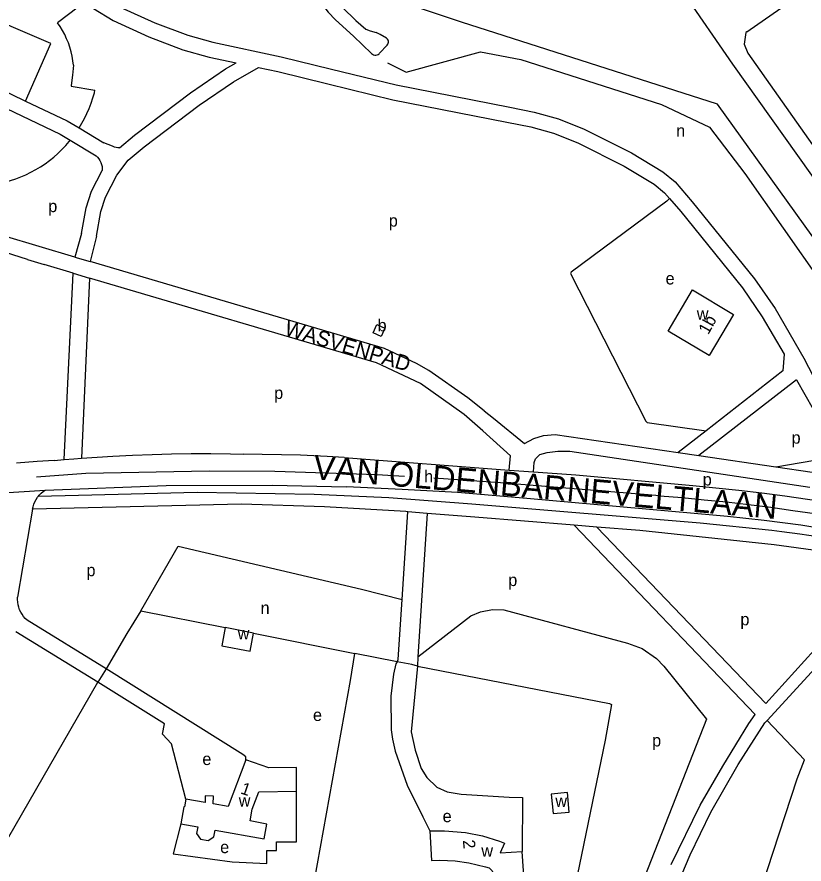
# Model space of a CAD drawing. Extents: x 162427 to 165104, y 384242 to 386287.
# Drawn here: x 162833.6 to 163093, y 385284.6 to 385563.5 of the extents above; entities that cross this region are included whole.
import ezdxf

# ---------------------------------------------------------------- set-up
doc = ezdxf.new("R2010")
doc.units = 0
for name, color, linetype in [('BLT_Basislijn', 7, 'Continuous'), ('BLT_Bebouwing', 7, 'Continuous'), ('BLT_Centroide', 7, 'Continuous'), ('BLT_Huisnummer', 7, 'Continuous'), ('BLT_Straatnaam', 7, 'Continuous'), ('BLT_Straatnaam_hoofdweg', 7, 'Continuous'), ('BLT_Vlakafsluiter', 7, 'Continuous')]:
    doc.layers.add(name, color=color, linetype=linetype)

msp = doc.modelspace()

# ---------------------------------------------------------------- linework, layer by layer
at = {"layer": 'BLT_Basislijn'}
for p, q in [((163074.07, 385558.59), (163110.58, 385584.14)), ((162853.74, 385566.74), (162846.99, 385561.61)), ((162953.08, 385551.58), (162955.6, 385554.29)), ((162824.38, 385541.58), (162836.46, 385535.85)), ((162851.46, 385540.73), (162859.33, 385539.43)), ((162854.09, 385526.99), (162862.24, 385522.09)), ((162851.16, 385522.92), (162859.67, 385517.81)), ((162865.15, 385520.94), (162862.24, 385522.09)), ((162837.14, 385483.62), (162842.56, 385481.97)), ((162852.73, 385484.48), (162857.74, 385483.02)), ((162852.12, 385479.12), (162842.56, 385481.97)), ((162849.18, 385417.79), (162852.12, 385479.12)), ((162852.12, 385479.12), (162857.5, 385477.49)), ((162857.5, 385477.49), (162854.91, 385418.26)), ((163090.51, 385444.08), (163058.29, 385419.08)), ((163060.7, 385427.28), (163051.43, 385420.09)), ((163010.97, 385426.02), (163051.43, 385420.09)), ((162941.38, 385418.48), (162935.87, 385418.75)), ((162941.38, 385418.48), (162995.84, 385414.29)), ((163051.43, 385420.09), (163058.29, 385419.08)), ((163058.29, 385419.08), (163083.72, 385415.35)), ((162840.26, 385417.1), (162833.42, 385416.61)), ((162845.92, 385417.51), (162840.26, 385417.1)), ((162845.92, 385417.51), (162849.18, 385417.79)), ((162995.84, 385414.29), (163003.86, 385413.73)), ((163083.72, 385415.35), (163095.61, 385413.61)), ((162838.73, 385401.42), (162833.82, 385372.49)), ((162960.57, 385371.71), (162962.45, 385400.6)), ((162968.83, 385400.07), (162965.69, 385352.84)), ((163017.2, 385396.15), (162984.46, 385398.77)), ((163017.2, 385396.15), (163076.9, 385333.85)), ((163024.7, 385395.55), (163017.2, 385396.15)), ((163024.7, 385395.55), (163080.36, 385337.47)), ((163080.36, 385337.47), (163121.81, 385383.22)), ((162874.46, 385367.97), (162902.26, 385362.46)), ((162863.02, 385348.85), (162836.97, 385364.91)), ((162860.27, 385344.53), (162833.28, 385361.09)), ((162911.61, 385360.62), (162944.93, 385353.93)), ((162958.89, 385351.17), (162944.93, 385353.93)), ((162965.69, 385352.84), (162965.6, 385349.76)), ((162863.02, 385348.85), (162860.27, 385344.53)), ((162963.73, 385350.33), (162958.89, 385351.17)), ((162965.6, 385349.76), (162963.73, 385350.33)), ((163080.8, 385331.81), (163093.14, 385318.96))]:
    msp.add_line(p, q, dxfattribs=at)
for points in [[(162761.2, 385522.51), (162766.48, 385530.94), (162788.41, 385566), (162791.77, 385571.66), (162794.41, 385575.12), (162797.5, 385577.98), (162799.64, 385579.2), (162802.6, 385580.51), (162808.08, 385582.95), (162814.65, 385584.84), (162822.48, 385586.18), (162824.7, 385586.14), (162827.51, 385585.55), (162831.36, 385584.11), (162837.28, 385580.8), (162858.83, 385566.3), (162865.3, 385562.36), (162877.09, 385557.03), (162888.31, 385552.73), (162896.96, 385550.32), (162905.89, 385548.44)], [(162922.1, 385587.98), (162922.54, 385586.04), (162923.76, 385585.16), (162926.09, 385582.79), (162927.4, 385581.27), (162929.16, 385579.75), (162932.92, 385576.17), (162934.92, 385574.11), (162938.91, 385568.91), (162940.88, 385566.6), (162945.28, 385562.36), (162948.62, 385559.54), (162949.98, 385558.93), (162952, 385558.44)], [(162916.4, 385584.93), (162917.45, 385584.86), (162918.26, 385584.17), (162922.97, 385580), (162926.8, 385576.15), (162931.92, 385570.8), (162936.11, 385565.09), (162938.57, 385562.64), (162944.56, 385557.26), (162950.46, 385551.47)], [(163053.01, 385571.86), (163069.39, 385548), (163103.5, 385500), (163138.29, 385450.78), (163142.13, 385444.88), (163144.53, 385439.97), (163145.57, 385436.28), (163145.97, 385432.21), (163145.34, 385429.37)], [(162867.64, 385566.79), (162879.02, 385561.65), (162889.87, 385557.49), (162898.15, 385555.18), (162920.71, 385550.41), (162937.22, 385546.38), (162958.59, 385541.16), (162996.04, 385533.78), (163004.04, 385532.2), (163012.04, 385530.03), (163020.48, 385526.63), (163036.1, 385518.74), (163046.44, 385512.58), (163050.5, 385509.22), (163056.14, 385502.71), (163076.67, 385477.33), (163083.41, 385467.5), (163092.94, 385451.2)], [(163116.12, 385462.98), (163064.49, 385534.84), (162980.05, 385561.82), (162964.58, 385567.01), (162964.39, 385567.3)], [(162836.46, 385535.85), (162844.79, 385554.75), (162818.33, 385566.15), (162812.27, 385551.72), (162801.8, 385556.33), (162796.54, 385544.37), (162805.66, 385540.36), (162811.36, 385541.63)], [(162852.25, 385547.65), (162852.07, 385549.14), (162851.81, 385550.63), (162851.47, 385552.1), (162851.06, 385553.54), (162850.56, 385554.97), (162849.99, 385556.36), (162849.35, 385557.73), (162848.64, 385559.06), (162847.86, 385560.35), (162846.99, 385561.61)], [(162955.41, 385556.57), (162953.31, 385557.79), (162952, 385558.44)], [(163074.07, 385558.59), (163073.78, 385558.45), (163073.18, 385554.63), (163074.49, 385551.59), (163145.21, 385451.38), (163149.2, 385444.54), (163150.89, 385439.83), (163151.59, 385436.07), (163151.22, 385429.35), (163150.93, 385427.49)], [(162955.6, 385554.29), (162955.81, 385554.56), (162955.95, 385554.88), (162956.02, 385555.22), (162956.01, 385555.57), (162955.92, 385555.9), (162955.76, 385556.21), (162955.53, 385556.47), (162955.41, 385556.57)], [(162950.46, 385551.47), (162950.77, 385551.24), (162951.12, 385551.08), (162951.49, 385551), (162951.88, 385550.99), (162952.26, 385551.06), (162952.61, 385551.21), (162952.93, 385551.43), (162953.08, 385551.58)], [(162955.7, 385548.45), (162961.84, 385545.4), (162986.37, 385552), (162999.63, 385549.49), (163045.96, 385534.68), (163061.82, 385527.19), (163073.48, 385511.96), (163123.98, 385439.93), (163131.85, 385428.71), (163141.25, 385424.64)], [(162852.25, 385547.65), (162851.92, 385544.32), (162851.5, 385541.01), (162851.46, 385540.73)], [(162859.77, 385491.36), (162861.22, 385499.46), (162862.81, 385504.19), (162866.55, 385511.46), (162870.27, 385516.35), (162875.49, 385520.72), (162893.66, 385534.49), (162904.99, 385542.15), (162913.21, 385546.89)], [(162867.37, 385520.44), (162872.37, 385524.63), (162890.75, 385538.56), (162902.34, 385546.4), (162905.89, 385548.44)], [(162913.21, 385546.89), (162919.6, 385545.54), (162936.03, 385541.53), (162957.52, 385536.28), (162995.08, 385528.87), (163002.9, 385527.33), (163010.44, 385525.28), (163018.41, 385522.07), (163033.69, 385514.36), (163043.55, 385508.48), (163046.99, 385505.63), (163048.59, 385503.79)], [(162854.09, 385526.99), (162855.03, 385528.54), (162855.89, 385530.14), (162856.69, 385531.77), (162857.41, 385533.44), (162858.05, 385535.13), (162858.62, 385536.86), (162859.12, 385538.6), (162859.33, 385539.43)], [(162822.45, 385536.96), (162847.84, 385524.91), (162851.16, 385522.92)], [(162836.46, 385535.85), (162850.21, 385529.32), (162854.09, 385526.99)], [(162852.73, 385484.48), (162829.23, 385491.51), (162815.77, 385495.86), (162796.25, 385503.93), (162783.67, 385510.02), (162761.2, 385522.51)], [(162822.62, 385507.91), (162824.42, 385508.1), (162826.22, 385508.37), (162828, 385508.71), (162829.76, 385509.14), (162831.51, 385509.64), (162833.23, 385510.22), (162834.92, 385510.87), (162836.59, 385511.6), (162838.21, 385512.4), (162839.81, 385513.27), (162841.36, 385514.21), (162842.87, 385515.21), (162844.33, 385516.29), (162845.75, 385517.42), (162847.11, 385518.62), (162848.42, 385519.88), (162849.68, 385521.19), (162850.87, 385522.56), (162851.16, 385522.92)], [(162867.37, 385520.44), (162866.8, 385520.44), (162866.25, 385520.52), (162865.71, 385520.68), (162865.15, 385520.94)], [(162837.14, 385483.62), (162807.68, 385493), (162793.85, 385498.57), (162759.31, 385518.12)], [(162859.67, 385517.81), (162860.16, 385517.34), (162860.6, 385516.81), (162860.97, 385516.24), (162861.27, 385515.63), (162861.49, 385514.98), (162861.64, 385514.32), (162861.71, 385513.64), (162861.71, 385512.96)], [(162854.85, 385492.24), (162856.37, 385500.7), (162858.19, 385506.14), (162861.71, 385512.96)], [(163048.59, 385503.79), (163047.8, 385502.89), (163016.21, 385479.55), (163015.99, 385479.01), (163040.81, 385430.41), (163041.32, 385430.02), (163060.7, 385427.28)], [(163048.59, 385503.79), (163052.31, 385499.5), (163072.66, 385474.34), (163079.19, 385464.82), (163086.37, 385452.53)], [(162854.85, 385492.24), (162852.73, 385484.48)], [(162859.77, 385491.36), (162857.74, 385483.02)], [(162987.6, 385433.84), (162982.19, 385438.08), (162969.31, 385447.1), (162965.27, 385449.46), (162954.72, 385454.34), (162857.74, 385483.02)], [(162995.84, 385414.29), (162996.24, 385418.97), (162987.15, 385427.3), (162980.93, 385432.66), (162966.54, 385442.85), (162952.07, 385449.62), (162857.5, 385477.49)], [(163086.37, 385452.53), (163085.95, 385446.99), (163060.7, 385427.28)], [(163092.94, 385451.2), (163100.4, 385436.75), (163108.94, 385419.04)], [(163090.51, 385444.08), (163095.96, 385434.43), (163102.8, 385420.27), (163102.7, 385419.23), (163102.04, 385418.37)], [(162987.6, 385433.84), (162990.63, 385431.42), (163000.82, 385423.08), (163003.92, 385424.75), (163007.1, 385425.75), (163010.97, 385426.02)], [(162854.91, 385418.26), (162865.23, 385418.94), (162871.68, 385419.26), (162878.14, 385419.5), (162884.59, 385419.66), (162891.05, 385419.74), (162897.51, 385419.73), (162903.96, 385419.65), (162908.15, 385419.56)], [(162935.87, 385418.75), (162927.03, 385419.18), (162908.15, 385419.56)], [(163003.86, 385413.73), (163004.08, 385416.82), (163004.53, 385418.02), (163005.92, 385419.41), (163008.29, 385420.11), (163011.86, 385420.54), (163015.8, 385420.54), (163094.87, 385408.66)], [(163083.72, 385415.35), (163100.41, 385418.22), (163102.04, 385418.37)], [(162849.18, 385417.79), (162852.35, 385418.07), (162854.91, 385418.26)], [(162840.06, 385412.11), (162856.33, 385413.29), (162896.97, 385414.1), (162918.55, 385413.98), (162952.2, 385412.92), (162961.33, 385412.37)], [(163003.86, 385413.73), (163017.77, 385412.76), (163056.37, 385409.27)], [(163045.45, 385405.86), (162992.99, 385410.16), (162970.95, 385411.68)], [(162840.56, 385405.58), (162840.98, 385406.1), (162841.59, 385406.73), (162842.25, 385407.3), (162842.86, 385407.73)], [(162842.86, 385407.73), (162882.79, 385409.24), (162917.68, 385409.39), (162942.18, 385408.77)], [(162978.79, 385406.89), (162960.53, 385407.96), (162942.18, 385408.77)], [(163056.37, 385409.27), (163063.93, 385408.53), (163071.49, 385407.71), (163079.04, 385406.81), (163086.58, 385405.83), (163094.1, 385404.77), (163101.62, 385403.64), (163109.12, 385402.42), (163116.61, 385401.12), (163121.43, 385400.25)], [(162838.73, 385401.42), (162838.92, 385402.27), (162839.19, 385403.1), (162839.53, 385403.91), (162839.95, 385404.68), (162840.43, 385405.41), (162840.56, 385405.58)], [(162983.51, 385403.11), (162956.12, 385405.19), (162931.57, 385406.33), (162893.03, 385406.89), (162853.93, 385405.95), (162840.56, 385405.58)], [(163064.08, 385399.33), (163001.65, 385405), (162978.79, 385406.89)], [(163045.45, 385405.86), (163052.78, 385405.26), (163060.1, 385404.58), (163067.41, 385403.82), (163074.71, 385402.98), (163082.01, 385402.06), (163089.29, 385401.06), (163096.57, 385399.98), (163103.83, 385398.82), (163111.08, 385397.58), (163115.29, 385396.83)], [(162962.45, 385400.6), (162961.79, 385400.66), (162934.97, 385402.17), (162907.58, 385403.11), (162838.73, 385401.42)], [(163082.4, 385394.42), (163058.69, 385396.88), (162983.51, 385403.11)], [(162968.83, 385400.07), (162962.45, 385400.6)], [(162984.46, 385398.77), (162968.83, 385400.07)], [(163157.11, 385381.75), (163151.27, 385383.45), (163145.4, 385385.07), (163139.52, 385386.61), (163133.62, 385388.08), (163127.7, 385389.46), (163121.76, 385390.77), (163115.81, 385392), (163109.84, 385393.16), (163103.86, 385394.23), (163097.86, 385395.23), (163091.85, 385396.14), (163085.82, 385396.98), (163079.79, 385397.74), (163073.75, 385398.41), (163067.7, 385399.01), (163064.08, 385399.33)], [(163083.15, 385389.69), (163038.86, 385394.42), (163024.7, 385395.55)], [(163161.53, 385377.68), (163155.81, 385379.41), (163150.06, 385381.05), (163144.29, 385382.62), (163138.5, 385384.11), (163132.69, 385385.53), (163126.87, 385386.86), (163121.02, 385388.12), (163115.16, 385389.3), (163109.29, 385390.4), (163103.4, 385391.43), (163097.49, 385392.37), (163091.58, 385393.23), (163085.65, 385394.02), (163082.4, 385394.42)], [(162874.46, 385367.97), (162886.68, 385389.28), (162947.16, 385375.1), (162960.57, 385371.71)], [(163121.81, 385383.22), (163121.48, 385383.3), (163115.93, 385384.46), (163110.35, 385385.55), (163104.76, 385386.55), (163099.16, 385387.48), (163093.54, 385388.33), (163087.92, 385389.1), (163083.15, 385389.69)], [(163129.12, 385354.39), (163124.66, 385363.72), (163121.61, 385375.54), (163121.26, 385375.58), (163118.48, 385372.93), (163080.8, 385331.81)], [(162836.97, 385364.91), (162836.35, 385365.49), (162835.78, 385366.14), (162835.28, 385366.83), (162834.85, 385367.57), (162834.49, 385368.34), (162834.2, 385369.15), (162833.98, 385369.98), (162833.85, 385370.82), (162833.79, 385371.68), (162833.82, 385372.49)], [(162958.89, 385351.17), (162959.24, 385351.94), (162960.57, 385371.71)], [(162965.69, 385352.84), (162983.21, 385366.35), (162986.39, 385367.67), (162990.33, 385368.38), (162994.07, 385368.33), (163034.75, 385357.35), (163039.59, 385355.6), (163044.36, 385352.23), (163046.8, 385349.75), (163060.77, 385332.28), (163028.94, 385251.16), (163027.67, 385248.94), (163019.63, 385237.96), (163009.41, 385217.72), (162996.31, 385190.48), (162992.28, 385189.49)], [(162874.46, 385367.97), (162869.78, 385360.52), (162863.02, 385348.85)], [(162926.02, 385245.83), (162927.74, 385257.26), (162943.57, 385345.06), (162944.93, 385353.93)], [(162909.06, 385318.93), (162909.04, 385319.93), (162908.03, 385320.69), (162863.02, 385348.85)], [(162958.89, 385351.17), (162958.43, 385350.47), (162957.68, 385347.08), (162956.76, 385339.89), (162956.88, 385328.83), (162957.32, 385325.72), (162958.28, 385321.8), (162962.24, 385310.61), (162967.38, 385300.17), (162969.63, 385295.5)], [(162965.6, 385349.76), (162963.55, 385328.15), (162964.82, 385322.04), (162966.83, 385316), (162968.7, 385313.06), (162972.01, 385309.91), (162975.36, 385308.36), (162980.02, 385307.56), (162995.85, 385306.61)], [(162965.6, 385349.76), (163028.81, 385337.47), (163029.51, 385337.1), (163027.38, 385325.35), (163011.22, 385246.68), (163005.62, 385234.36), (162999.14, 385223.47), (162982.5, 385215.51)], [(162834.05, 385253.2), (162827.34, 385264.48), (162824.86, 385269.68), (162823.82, 385274.93), (162824.44, 385281.17), (162826.19, 385285.52), (162860.27, 385344.53)], [(162889.31, 385305.99), (162884.53, 385324.17), (162881.62, 385327.4), (162882.18, 385330.71), (162860.27, 385344.53)], [(163049.23, 385284.4), (163058.77, 385304.03), (163066.15, 385316.81), (163074.73, 385330.89), (163076.9, 385333.85)], [(163050.17, 385099.92), (163043.85, 385110.36), (163040, 385117.94), (163035.74, 385127.32), (163031.74, 385137.7), (163028.59, 385148.33), (163025.01, 385164.11), (163024.68, 385166.51), (163024.35, 385174.43), (163024.41, 385185.63), (163024.9, 385191.54), (163028.4, 385210.46), (163031.8, 385223.24), (163039.95, 385248.68), (163044.77, 385262.46), (163055.44, 385287.67), (163062.28, 385301.64), (163071.2, 385317.38), (163080.08, 385331.06), (163080.8, 385331.81)], [(163050.17, 385099.92), (163057.2, 385114.94), (163058.93, 385119.41), (163060.54, 385129.27), (163060.68, 385134.28), (163056.7, 385183.49), (163052.96, 385210.26), (163053.62, 385218.8), (163055.24, 385224.74), (163057.81, 385232.41), (163074.99, 385264.65), (163090.72, 385312.68), (163093.14, 385318.96)], [(162887.61, 385297.81), (162885.04, 385287.93), (162904.51, 385285.35), (162915.96, 385284.78), (162915.96, 385289.07), (162919.11, 385289.07), (162919.11, 385291.94), (162925.7, 385291.94), (162925.7, 385308.54)], [(162995.85, 385306.61), (163000.14, 385306.55), (163000.1, 385288.75)]]:
    msp.add_lwpolyline(points, dxfattribs=at)
at = {"layer": 'BLT_Bebouwing'}
msp.add_line((162911.61, 385360.62), (162902.26, 385362.46), dxfattribs=at)
for points in [[(163056.25, 385473.64), (163069.76, 385465.57), (163061.67, 385452.03), (163048.16, 385460.11)], [(162950.95, 385459.52), (162952.16, 385462.24), (162954.85, 385461.04), (162953.64, 385458.32)], [(163014.99, 385308.14), (163009.64, 385307.63), (163010.25, 385301.21), (163015.61, 385301.72)]]:
    msp.add_lwpolyline(points, close=True, dxfattribs=at)
for points in [[(162902.26, 385362.46), (162901.09, 385356.49), (162910.43, 385354.65), (162911.61, 385360.62)], [(162909.06, 385318.93), (162903.23, 385303.52), (162898.29, 385304.41), (162898.36, 385306.96), (162895.66, 385307.03), (162895.61, 385304.86), (162889.31, 385305.99)], [(162925.7, 385308.54), (162925.75, 385316.34), (162916.61, 385316.32), (162909.06, 385318.93)], [(162887.61, 385297.81), (162893.26, 385296.8), (162892.81, 385294.67), (162894.08, 385292.8), (162896.67, 385292.33), (162898.53, 385293.51), (162898.91, 385295.79), (162915.12, 385292.88), (162916, 385297.77), (162910.43, 385298.77), (162911.13, 385302.64), (162913.36, 385308.39), (162925.7, 385308.54)], [(162889.31, 385305.99), (162888.85, 385303.41), (162888.62, 385303.45), (162887.61, 385297.81)], [(162969.63, 385295.5), (162969.63, 385295.5), (162974.51, 385295.5), (162981.41, 385295.01), (162987.05, 385293.93), (162992.58, 385292.16), (162994.21, 385291.52), (162992.87, 385288.25), (163000.1, 385288.75)], [(162969.63, 385295.5), (162970.26, 385285.79), (162973, 385285.9), (162978.05, 385285.66), (162982.5, 385284.99), (162987.98, 385283.71), (162989.2, 385283.3), (162990.21, 385282.38), (162990.64, 385281.29), (162991.35, 385270.58), (163001.24, 385271.23), (163000.1, 385288.75)]]:
    msp.add_lwpolyline(points, dxfattribs=at)
at = {"layer": 'BLT_Vlakafsluiter'}
msp.add_line((162826.5, 385406.71), (162842.86, 385407.73), dxfattribs=at)

# ---------------------------------------------------------------- texts
at = {"layer": 'BLT_Centroide'}
for s, p in [('n', (163050.83, 385524.1)), ('p', (162843.93, 385499.27)), ('p', (162956.14, 385494.49)), ('e', (163047.34, 385475.45)), ('w', (163057.62, 385463.84)), ('b', (162952.44, 385460.02)), ('p', (162918.37, 385437.75)), ('p', (163088.85, 385423.02)), ('h', (162967.78, 385410.24)), ('p', (163059.58, 385409.25)), ('p', (162856.51, 385379.38)), ('p', (162995.5, 385376.14)), ('n', (162913.9, 385366.98)), ('p', (163071.99, 385363.21)), ('w', (162906.34, 385358.56)), ('e', (162931.15, 385331.7)), ('p', (163042.9, 385323.32)), ('e', (162894.7, 385317.2)), ('w', (162906.69, 385303.52)), ('w', (163011.01, 385303.42)), ('e', (162973.87, 385298.38)), ('e', (162900.57, 385288.19)), ('w', (162986.62, 385287))]:
    msp.add_text(s, height=4, dxfattribs=at).set_placement(p)
at = {"layer": 'BLT_Huisnummer'}
for s, rotation, p in [('1b', 61.0718, (163061.41, 385458.71)), ('1', 340.9068, (162907.02, 385307.91)), ('2', 276.0084, (162980.5, 385292.39))]:
    msp.add_text(s, height=4, rotation=rotation, dxfattribs=at).set_placement(p)
at = {"layer": 'BLT_Straatnaam'}
msp.add_text('WASVENPAD', height=5, rotation=343.3556, dxfattribs=at).set_placement((162921.44, 385458.92))
at = {"layer": 'BLT_Straatnaam_hoofdweg'}
msp.add_text('VAN OLDENBARNEVELTLAAN', height=8, rotation=355.0684, dxfattribs=at).set_placement((162931.01, 385411.37))

doc.saveas('drawing.dxf')
